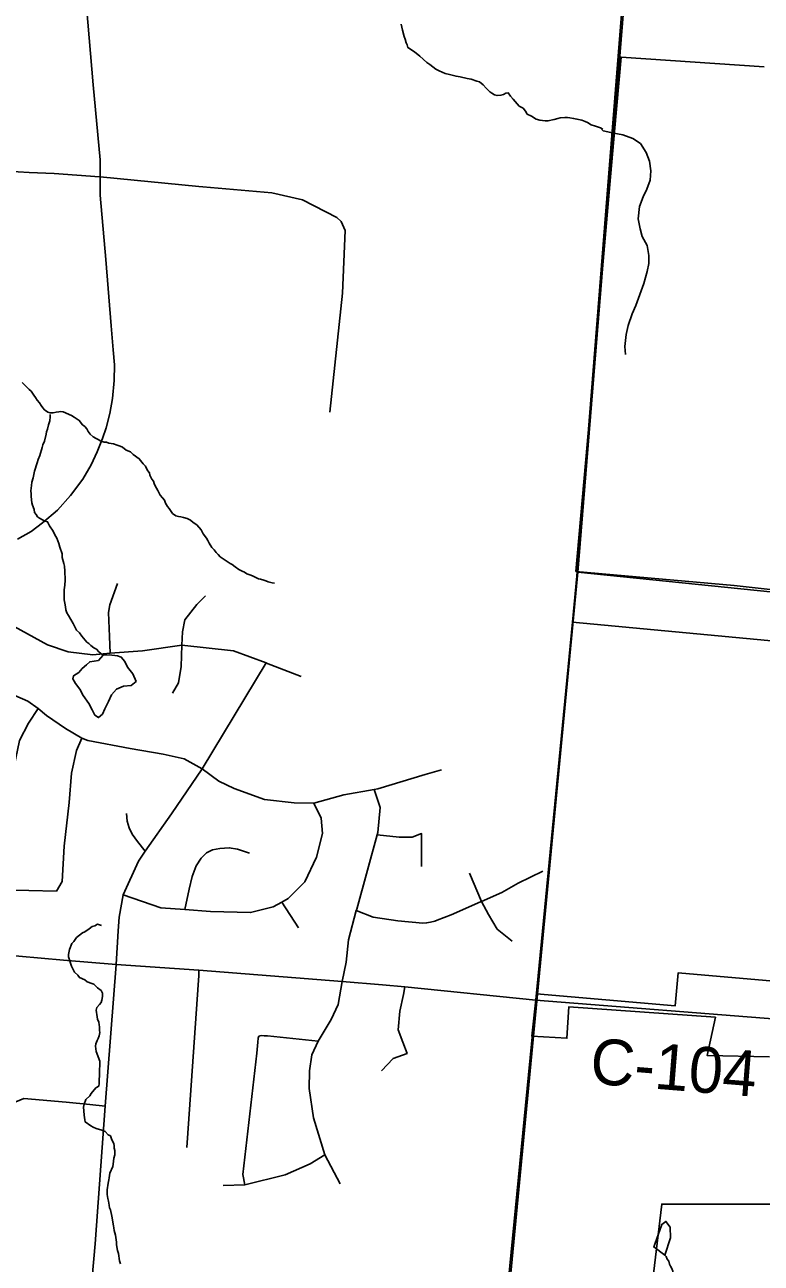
# Model space of a CAD drawing. Extents: x -7.3 to 34, y 0 to 22.
# Drawn here: x 3.68 to 4.595, y 15.258 to 16.795 of the extents above; entities that cross this region are included whole.
import ezdxf

# ---------------------------------------------------------------- set-up
doc = ezdxf.new("R2010")
doc.units = 0
for name, color, linetype in [('GM_X_City_Street', 7, 'Continuous'), ('GM_X_Corporation', 7, 'Continuous'), ('GM_X_County_Road', 7, 'Continuous'), ('GM_X_County_Road_Text', 7, 'Continuous'), ('GM_X_Minor_Lake', 7, 'Continuous'), ('GM_X_Minor_River', 7, 'Continuous')]:
    doc.layers.add(name, color=color, linetype=linetype)

msp = doc.modelspace()

# ---------------------------------------------------------------- linework, layer by layer
at = {"layer": 'GM_X_City_Street'}
for p, q in [((4.2477, 15.7066), (4.2328, 15.742)), ((4.0204, 15.6738), (3.9996, 15.706))]:
    msp.add_line(p, q, dxfattribs=at)
for points in [[(3.3258, 16.1729), (3.3317, 16.1717), (3.3428, 16.1694), (3.3647, 16.1606), (3.386, 16.1536), (3.4317, 16.1484), (3.4649, 16.146), (3.4918, 16.145), (3.5197, 16.1405), (3.5462, 16.1287), (3.5691, 16.1116), (3.6036, 16.086), (3.632, 16.0675), (3.6506, 16.0574), (3.7088, 16.0253), (3.7341, 16.0168), (3.7648, 16.013), (3.7864, 16.0151), (3.8265, 16.018), (3.8756, 16.0249), (3.9397, 16.0179), (3.9801, 16.0031), (3.9807, 16.0028), (4.0236, 15.9862)], [(3.7864, 16.0151), (3.7857, 16.0356), (3.7844, 16.0653), (3.7861, 16.0751), (3.7957, 16.1015)], [(3.8756, 16.0249), (3.8763, 16.0416), (3.8792, 16.0563), (3.8941, 16.0755), (3.9049, 16.0863)], [(3.8638, 15.9654), (3.8712, 15.9782), (3.8747, 15.9983), (3.8756, 16.0249)], [(3.6375, 15.97), (3.6585, 15.9666), (3.684, 15.9555), (3.6971, 15.9464), (3.7075, 15.9375), (3.731, 15.9214), (3.7512, 15.9094), (3.7588, 15.9067), (3.8115, 15.8965), (3.8522, 15.8895), (3.8783, 15.8839), (3.9009, 15.8712), (3.9216, 15.8562), (3.9406, 15.8468), (3.9784, 15.8335), (4.0152, 15.8291), (4.0396, 15.8287), (4.0767, 15.8393), (4.1145, 15.8459), (4.1191, 15.8467), (4.1778, 15.8643), (4.1983, 15.8701)], [(3.6448, 15.6413), (3.6486, 15.6877), (3.6511, 15.7213), (3.6647, 15.8626), (3.6738, 15.9065), (3.6851, 15.928), (3.6971, 15.9464)], [(3.7197, 15.7193), (3.7268, 15.7313), (3.7295, 15.7754), (3.7357, 15.8295), (3.7384, 15.8659), (3.7448, 15.8941), (3.7512, 15.9094)], [(3.5012, 15.8704), (3.4969, 15.8105), (3.493, 15.7619), (3.4984, 15.745), (3.5152, 15.7333), (3.582, 15.7264), (3.615, 15.7233), (3.6511, 15.7213), (3.7197, 15.7193)], [(4.0722, 15.3559), (4.0531, 15.3919), (4.0392, 15.438), (4.0339, 15.4745), (4.0342, 15.4963), (4.0371, 15.5163), (4.0447, 15.5331), (4.0612, 15.5601), (4.0696, 15.5786), (4.0748, 15.6073), (4.0796, 15.6314), (4.0825, 15.6592), (4.0923, 15.6954), (4.0928, 15.6973), (4.106, 15.7456), (4.1183, 15.7893), (4.1191, 15.7925), (4.1221, 15.8232), (4.1145, 15.8459)], [(3.8027, 15.7148), (3.8496, 15.6987), (3.8791, 15.6966), (3.9111, 15.6943), (3.9609, 15.6929), (3.9888, 15.7002), (3.9996, 15.706), (4.0078, 15.7105), (4.0283, 15.731), (4.043, 15.7617), (4.0503, 15.791), (4.0488, 15.8101), (4.0396, 15.8287)], [(3.8301, 15.7691), (3.8204, 15.7812), (3.8139, 15.7902), (3.8099, 15.798), (3.8076, 15.8066), (3.8067, 15.816)], [(4.1183, 15.7893), (4.1455, 15.7866), (4.1616, 15.7866), (4.1734, 15.791), (4.1734, 15.75)], [(3.8791, 15.6966), (3.8848, 15.7218), (3.8884, 15.7379), (3.8935, 15.7508), (3.8996, 15.7604), (3.906, 15.7672), (3.9137, 15.7708), (3.9228, 15.7723), (3.9344, 15.7734), (3.9448, 15.7716), (3.9595, 15.7665)], [(4.0923, 15.6954), (4.1133, 15.687), (4.144, 15.6826), (4.1748, 15.6797), (4.1796, 15.6801), (4.1845, 15.681), (4.1897, 15.6824), (4.1927, 15.6835), (4.21, 15.69), (4.2466, 15.7061), (4.2477, 15.7066), (4.273, 15.7178), (4.2935, 15.7295), (4.3242, 15.7442)], [(4.2861, 15.6574), (4.2674, 15.6724), (4.2566, 15.6905), (4.2477, 15.7066)], [(3.8816, 15.4013), (3.8968, 15.6147), (3.8968, 15.6212)], [(4.1235, 15.4966), (4.138, 15.5116), (4.1554, 15.518), (4.1502, 15.5319), (4.1444, 15.5473), (4.1465, 15.5705), (4.1511, 15.5911), (4.1525, 15.6007)], [(3.9536, 15.3549), (3.9511, 15.3676), (3.9686, 15.5182), (3.97, 15.5319), (3.9704, 15.5371), (3.9712, 15.5394), (3.9727, 15.5399), (3.9745, 15.5401), (3.9778, 15.54), (3.9819, 15.5398), (4.0447, 15.5331)], [(3.5907, 15.0689), (3.5963, 15.1104), (3.5944, 15.1486), (3.594, 15.1868), (3.6093, 15.238), (3.6209, 15.3322), (3.6257, 15.3785), (3.6286, 15.4067), (3.6341, 15.4266), (3.6437, 15.4409), (3.6549, 15.4513), (3.6693, 15.4579), (3.6792, 15.4622), (3.7318, 15.4574), (3.7612, 15.4547), (3.7802, 15.4524)], [(3.9267, 15.3539), (3.9536, 15.3549), (4.0039, 15.3671), (4.0348, 15.3811), (4.0531, 15.3919)]]:
    msp.add_lwpolyline(points, dxfattribs=at)
at = {"layer": 'GM_X_Corporation'}
for points in [[(4.2701, 15.1232), (4.3152, 15.5847), (4.3609, 16.0535), (4.3664, 16.1106), (4.407, 16.6214), (4.447, 17.1255), (4.4477, 17.1339), (4.4511, 17.177), (4.4529, 17.1999), (4.4538, 17.2111), (4.4563, 17.2424), (4.3607, 17.2139), (4.2287, 17.1787), (4.0109, 17.1109), (3.7543, 17.039), (3.5614, 16.9883)], [(3.5614, 16.9883), (3.7543, 17.039), (4.0109, 17.1109), (4.2287, 17.1787), (4.3607, 17.2139), (4.4563, 17.2424), (4.4538, 17.2111), (4.4529, 17.1999), (4.4511, 17.177), (4.4477, 17.1339), (4.447, 17.1255), (4.407, 16.6214), (4.3664, 16.1106), (4.3609, 16.0535), (4.3152, 15.5847), (4.2701, 15.1232)], [(4.2701, 15.1232), (4.3152, 15.5847), (4.3609, 16.0535), (4.3664, 16.1106), (4.407, 16.6214), (4.447, 17.1255), (4.4477, 17.1339), (4.4511, 17.177), (4.4529, 17.1999), (4.4538, 17.2111), (4.4563, 17.2424), (4.3607, 17.2139), (4.2287, 17.1787), (4.0109, 17.1109), (3.7543, 17.039), (3.5614, 16.9883)], [(3.5614, 16.9883), (3.7543, 17.039), (4.0109, 17.1109), (4.2287, 17.1787), (4.3607, 17.2139), (4.4563, 17.2424), (4.4538, 17.2111), (4.4529, 17.1999), (4.4511, 17.177), (4.4477, 17.1339), (4.447, 17.1255), (4.407, 16.6214), (4.3664, 16.1106), (4.3609, 16.0535), (4.3152, 15.5847), (4.2701, 15.1232)], [(5.0141, 15.9921), (4.3609, 16.0535), (4.3664, 16.1106), (4.407, 16.6214), (4.4511, 17.177)], [(4.7717, 16.0755), (4.5915, 16.0956), (4.5616, 16.0989), (4.3651, 16.1166), (4.3789, 16.2741), (4.3905, 16.4066), (4.4072, 16.5969), (4.413, 16.6629), (4.4213, 16.7552), (4.5992, 16.7429)], [(4.6056, 15.5139), (4.5282, 15.5154), (4.5384, 15.563), (4.3564, 15.5759), (4.3539, 15.5368), (4.3105, 15.5393), (4.316, 15.5922), (4.4884, 15.5771), (4.492, 15.618), (4.7108, 15.5989)], [(4.4477, 15.1303), (4.4717, 15.3309), (4.6123, 15.3309)]]:
    msp.add_lwpolyline(points, dxfattribs=at)
for points in [[(5.4793, 17.0267), (5.3843, 16.0117), (4.3675, 16.1154), (4.4498, 17.1284)], [(4.3675, 16.1154), (5.3843, 16.0117), (5.2968, 14.9953), (4.2681, 15.0765)]]:
    msp.add_lwpolyline(points, close=True, dxfattribs=at)
at = {"layer": 'GM_X_County_Road'}
msp.add_line((4.3155, 15.5841), (4.798, 15.5458), dxfattribs=at)
for points in [[(3.6713, 16.1565), (3.6882, 16.1659), (3.7025, 16.1767), (3.7212, 16.1924), (3.7373, 16.2106), (3.7525, 16.2312), (3.7627, 16.2487), (3.7705, 16.2649), (3.7769, 16.2814), (3.7815, 16.295), (3.7861, 16.3126), (3.7893, 16.3314), (3.7916, 16.3534), (3.7918, 16.3729), (3.7903, 16.3915), (3.7877, 16.4213), (3.7809, 16.5037), (3.774, 16.5837), (3.774, 16.6064), (3.7742, 16.6275), (3.7653, 16.7206), (3.7554, 16.8379)], [(3.3806, 16.7168), (3.4407, 16.7108), (3.4738, 16.707), (3.5216, 16.7026), (3.5331, 16.7003), (3.5404, 16.6965), (3.5459, 16.6914), (3.5525, 16.6829), (3.5656, 16.6629), (3.577, 16.647), (3.5833, 16.6399), (3.5901, 16.6335), (3.5968, 16.6289), (3.6038, 16.6248), (3.614, 16.6206), (3.6237, 16.6179), (3.6342, 16.6163), (3.6585, 16.6136), (3.6858, 16.6117), (3.717, 16.6104), (3.773, 16.6064)], [(3.773, 16.6064), (3.774, 16.6064), (3.8966, 16.5945), (3.9015, 16.5941)], [(3.9015, 16.5941), (3.9872, 16.5866), (4.0253, 16.5778), (4.0682, 16.5558), (4.0733, 16.551), (4.0784, 16.54), (4.075, 16.4622), (4.0595, 16.3142)], [(3.7941, 15.6285), (3.7962, 15.6703), (3.7977, 15.6872), (3.8027, 15.7148), (3.8218, 15.7567), (3.8301, 15.7691), (3.8627, 15.8156), (3.9009, 15.8712), (3.9801, 16.0031)], [(3.4023, 15.6584), (3.6184, 15.6439), (3.6448, 15.6413), (3.7283, 15.634), (3.7941, 15.6285), (3.8968, 15.6212), (4.0748, 15.6073), (4.1247, 15.603), (4.1525, 15.6007), (4.3155, 15.5841)], [(3.7053, 14.6035), (3.7105, 14.6583), (3.7161, 14.7316), (3.7341, 14.9032), (3.7378, 14.9448), (3.7475, 15.054), (3.7678, 15.2815), (3.7802, 15.4524), (3.7941, 15.6285)]]:
    msp.add_lwpolyline(points, dxfattribs=at)
at = {"layer": 'GM_X_Minor_Lake'}
for points in [[(3.7672, 15.9381), (3.764, 15.9446), (3.76, 15.9527), (3.753, 15.9623), (3.7486, 15.9704), (3.7434, 15.9773), (3.7402, 15.9831), (3.741, 15.9869), (3.7475, 15.9909), (3.7518, 15.9958), (3.7569, 16.0006), (3.7611, 16.0043), (3.7718, 16.006), (3.7776, 16.0125)], [(3.7776, 16.0125), (3.7852, 16.0129), (3.7954, 16.0116), (3.8003, 16.01), (3.8048, 16.0046), (3.808, 15.9977), (3.8147, 15.9892), (3.8186, 15.98), (3.8124, 15.9748), (3.8029, 15.9742), (3.7945, 15.9702), (3.7883, 15.9631), (3.7843, 15.9549), (3.7799, 15.9458), (3.7768, 15.9394), (3.7721, 15.935), (3.7672, 15.9381)], [(4.4756, 15.2676), (4.4825, 15.2891), (4.4821, 15.3024), (4.4769, 15.3094), (4.4719, 15.3057), (4.4631, 15.2813)], [(4.4631, 15.2813), (4.4618, 15.2778), (4.4756, 15.2676)]]:
    msp.add_lwpolyline(points, dxfattribs=at)
at = {"layer": 'GM_X_Minor_River'}
for points in [[(4.1479, 16.7962), (4.149, 16.7924), (4.1497, 16.7886), (4.1519, 16.7806), (4.153, 16.7775), (4.1541, 16.773), (4.1556, 16.7703), (4.1563, 16.7669), (4.1646, 16.7615), (4.171, 16.7561), (4.1797, 16.7485), (4.1838, 16.7458), (4.1909, 16.74), (4.1951, 16.7381), (4.2026, 16.7346), (4.2079, 16.7334), (4.2162, 16.7314), (4.2215, 16.7306), (4.2298, 16.7286), (4.2351, 16.7278), (4.2419, 16.7251), (4.2453, 16.7243), (4.2498, 16.7205), (4.2535, 16.7167), (4.2581, 16.7121), (4.2607, 16.7105), (4.2641, 16.7082), (4.2671, 16.7074), (4.272, 16.7078), (4.275, 16.7089), (4.2781, 16.7104), (4.2811, 16.7107), (4.2837, 16.7065), (4.2871, 16.7027), (4.2946, 16.6943), (4.2995, 16.6916), (4.3025, 16.6882)], [(4.3025, 16.6882), (4.3047, 16.6843), (4.31, 16.6816), (4.3157, 16.6782), (4.3202, 16.677), (4.327, 16.6758), (4.3304, 16.6758), (4.338, 16.6776), (4.3425, 16.6791), (4.3456, 16.6798), (4.3512, 16.6801), (4.3546, 16.6801), (4.3577, 16.6797), (4.3622, 16.6789), (4.3663, 16.6781), (4.3724, 16.6769), (4.3765, 16.6753), (4.3795, 16.6738), (4.3841, 16.6711), (4.3893, 16.6695), (4.3958, 16.6672), (4.3984, 16.6657)], [(4.3958, 16.6672), (4.3989, 16.6636), (4.4121, 16.6606), (4.4234, 16.6585), (4.4358, 16.654), (4.4455, 16.6477), (4.4524, 16.6368), (4.4567, 16.6261), (4.4583, 16.6139), (4.4572, 16.6022), (4.4531, 16.5913), (4.4487, 16.5815), (4.4442, 16.5695), (4.4423, 16.5543), (4.445, 16.5421), (4.4474, 16.5325), (4.4536, 16.521), (4.4559, 16.5088), (4.4556, 16.4989), (4.4535, 16.4891), (4.4493, 16.474), (4.4444, 16.4605), (4.4395, 16.4469), (4.435, 16.4364), (4.4301, 16.4217), (4.4275, 16.4108), (4.426, 16.396), (4.4269, 16.3857)], [(3.6772, 16.351), (3.6828, 16.3453), (3.6858, 16.3426), (3.6885, 16.3403), (3.6918, 16.3353), (3.6937, 16.3323), (3.6956, 16.3292), (3.6986, 16.3258), (3.7008, 16.3227), (3.7027, 16.3197), (3.7049, 16.317), (3.7091, 16.3143), (3.7121, 16.3135), (3.7155, 16.3135), (3.7193, 16.3142), (3.7227, 16.3146), (3.7253, 16.3149), (3.728, 16.3145), (3.731, 16.3133), (3.7355, 16.3114), (3.7385, 16.3102), (3.7416, 16.3079), (3.7453, 16.3056), (3.748, 16.3041), (3.7521, 16.2987), (3.7551, 16.2964), (3.7573, 16.2934), (3.7592, 16.2903), (3.7618, 16.2869), (3.7652, 16.2838), (3.769, 16.2815), (3.7716, 16.2803), (3.775, 16.2784), (3.7791, 16.2772), (3.7818, 16.2768), (3.7848, 16.2757), (3.7905, 16.2749), (3.795, 16.2733), (3.7988, 16.2721), (3.8018, 16.2706), (3.8063, 16.2671), (3.8116, 16.2648), (3.815, 16.2617), (3.8225, 16.2564), (3.8274, 16.2503), (3.8304, 16.2472), (3.833, 16.2419), (3.8352, 16.2388), (3.8359, 16.2361), (3.8382, 16.2312), (3.8401, 16.2285), (3.8412, 16.2255), (3.8423, 16.2228), (3.8441, 16.2198), (3.8456, 16.2171), (3.8486, 16.211), (3.8516, 16.2079), (3.8539, 16.2049), (3.8554, 16.2014), (3.8576, 16.1973), (3.8598, 16.1946), (3.864, 16.1885), (3.8681, 16.1854), (3.8715, 16.1846), (3.8741, 16.1842)], [(3.7121, 16.3112), (3.7121, 16.3086), (3.7116, 16.3037), (3.7097, 16.2984), (3.7085, 16.2931), (3.7074, 16.2897), (3.707, 16.287), (3.7047, 16.2783), (3.7027, 16.2738), (3.702, 16.2704), (3.6992, 16.2605), (3.6969, 16.2556), (3.6958, 16.2515), (3.695, 16.2488), (3.6931, 16.2435), (3.6923, 16.2409), (3.6907, 16.2329), (3.6892, 16.2272), (3.6887, 16.2231), (3.6879, 16.2166), (3.6883, 16.2128), (3.6883, 16.2094), (3.6893, 16.2018), (3.6901, 16.1988), (3.6919, 16.1935), (3.6923, 16.1897), (3.6945, 16.187), (3.696, 16.1843), (3.6987, 16.1828), (3.7054, 16.1789), (3.7088, 16.1781), (3.7111, 16.1732), (3.7156, 16.1667), (3.7178, 16.1618), (3.72, 16.1576), (3.7226, 16.1511), (3.7241, 16.1465), (3.7267, 16.1382), (3.727, 16.1336), (3.7289, 16.1264), (3.7296, 16.123), (3.7303, 16.1169), (3.7303, 16.1142), (3.7306, 16.1085), (3.7306, 16.1055), (3.7302, 16.0994), (3.7298, 16.0964), (3.7294, 16.0938), (3.7293, 16.0812), (3.73, 16.0771), (3.7308, 16.0725), (3.7315, 16.0687), (3.7326, 16.0649), (3.7345, 16.0619), (3.7404, 16.0519), (3.7416, 16.0493), (3.7445, 16.0436), (3.7483, 16.0401), (3.7513, 16.0363), (3.7554, 16.0313), (3.7573, 16.0287), (3.7599, 16.0271), (3.7625, 16.0244), (3.7663, 16.0217), (3.7693, 16.0198), (3.7723, 16.0168), (3.775, 16.0145), (3.7776, 16.0125)], [(3.8741, 16.1842), (3.8775, 16.1834), (3.8821, 16.1822), (3.8862, 16.1803), (3.8896, 16.1772), (3.8941, 16.1742), (3.8994, 16.168), (3.902, 16.1631), (3.9061, 16.1577), (3.908, 16.1547), (3.9094, 16.1516), (3.9128, 16.1463), (3.9158, 16.1432), (3.9181, 16.1398), (3.9207, 16.1375), (3.9233, 16.1348), (3.9305, 16.1298), (3.9354, 16.1264), (3.938, 16.1252), (3.9418, 16.1221), (3.9463, 16.1191), (3.9504, 16.1168), (3.9534, 16.1156), (3.9564, 16.1137), (3.9598, 16.1121), (3.9632, 16.111), (3.9659, 16.1098), (3.9708, 16.1075), (3.9734, 16.1071), (3.9772, 16.1055), (3.9798, 16.1047), (3.9828, 16.1036), (3.9877, 16.1024), (3.9908, 16.102)], [(3.7482, 15.6647), (3.752, 15.6677), (3.755, 15.6691), (3.7604, 15.6729), (3.7642, 15.6755), (3.7672, 15.6766), (3.7706, 15.6785), (3.7755, 15.6769)], [(3.7993, 15.2569), (3.7982, 15.2603), (3.7967, 15.2694), (3.7956, 15.2732), (3.7945, 15.2805), (3.7942, 15.2835), (3.7931, 15.2922), (3.7916, 15.2983), (3.7909, 15.3013), (3.7906, 15.304), (3.7898, 15.3086), (3.7895, 15.3112), (3.7887, 15.3158), (3.7869, 15.3238), (3.7858, 15.3264), (3.7854, 15.3295), (3.7843, 15.3344), (3.7836, 15.3378), (3.7829, 15.3428), (3.7829, 15.3488), (3.7841, 15.3568), (3.7849, 15.3609), (3.7853, 15.3636), (3.7861, 15.3693), (3.7896, 15.3776), (3.79, 15.3806), (3.7912, 15.3878), (3.7923, 15.392), (3.7924, 15.3973), (3.7916, 15.4003), (3.7913, 15.4034), (3.7909, 15.406), (3.7887, 15.4106), (3.7868, 15.4155), (3.7838, 15.4171), (3.7801, 15.4209), (3.7763, 15.4228), (3.7691, 15.4248), (3.7654, 15.4263), (3.7623, 15.4283), (3.7556, 15.4329), (3.7548, 15.4355), (3.7545, 15.4386), (3.7541, 15.4412), (3.7538, 15.4469), (3.7534, 15.4511), (3.7542, 15.4549), (3.7562, 15.4609), (3.7611, 15.4654), (3.763, 15.4681), (3.7687, 15.4752), (3.7722, 15.4775), (3.7726, 15.4805), (3.7726, 15.4832), (3.7734, 15.4926), (3.7735, 15.5082), (3.7691, 15.5204), (3.7684, 15.5272), (3.7688, 15.5298), (3.7703, 15.534), (3.7715, 15.5366), (3.7726, 15.5397), (3.7738, 15.5438), (3.7734, 15.5465), (3.7731, 15.551), (3.7727, 15.5537), (3.7724, 15.5567), (3.7709, 15.5605), (3.7705, 15.5636), (3.7691, 15.5719), (3.7698, 15.575), (3.7733, 15.5787), (3.7752, 15.5814), (3.7763, 15.584), (3.7768, 15.5886), (3.7768, 15.5927), (3.7753, 15.5961), (3.7708, 15.5996), (3.7663, 15.6042), (3.7636, 15.605), (3.758, 15.6069), (3.755, 15.6092), (3.7482, 15.6123), (3.7463, 15.615), (3.7422, 15.6188), (3.7403, 15.6223), (3.7385, 15.6264), (3.7348, 15.6379), (3.7348, 15.6409), (3.736, 15.647), (3.739, 15.6545), (3.7413, 15.6571), (3.7448, 15.662), (3.7482, 15.6647)], [(4.4848, 15.2385), (4.4854, 15.2476), (4.4843, 15.2511), (4.4825, 15.2538), (4.4814, 15.2565), (4.4804, 15.2599), (4.4785, 15.2626), (4.4771, 15.2657), (4.4756, 15.2676)]]:
    msp.add_lwpolyline(points, dxfattribs=at)

# ---------------------------------------------------------------- texts
at = {"layer": 'GM_X_County_Road_Text'}
msp.add_text('C-104', height=0.05682, rotation=355.3795, dxfattribs=at).set_placement((4.3814, 15.4808))

doc.saveas('drawing.dxf')
